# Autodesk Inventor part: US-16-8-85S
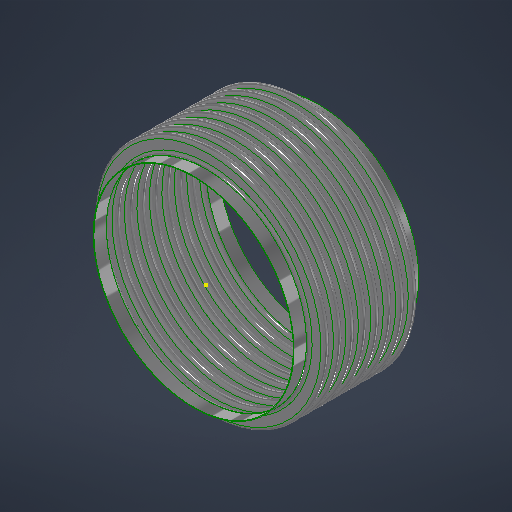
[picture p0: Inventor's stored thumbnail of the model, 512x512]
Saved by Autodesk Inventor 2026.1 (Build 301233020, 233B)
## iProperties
Category: 18 GA (0.048 THICK)
RuleStatus: InUse
Created: 2026-07
Part Number: US-16-8-85S
Project: =STOCK BELLOWS: <Stock Number><SFILL>
Material: ASTM A240-304
Description: =STOCK BELLOWS: <Stock Number>, <SID_> I.D., <SOD_> O.D., <SPLY_> PLY, <Category>, <SNET_CONS> CONS.<PITCH_><STANGENT_> TANGENT<SFILL>
Document SubType Name: Sheet Metal
Designer: LC
Stock Number: U.S-16-8-85S
Surface Area: 659.127 cm^2
Volume: 56.61 cm^3
Sheet Metal Rule: Default
Appearance: STAINLESS STEEL
NET_TUBE: 3.428
COUNTER: 1.500
PBAR: 1.214
PSET: 5.356
PLY: 2
CONS: 2
THK: 0.036
ID: 4.500
OD: 5.500
CONS_: 2
TANGENT: 0.500
PITCH: 0.375
BELLOWS_UPSET: 0.000
NET_CONS: 2
S_CONS: 0
Description_Units: 0
ID_M: 114.30 mm
OD_M: 139.70 mm
THK_M: 0.91 mm
ID_U: 4.500 in
OD_U: 5.500 in
THK_U: 0.036 in
TANGENT2: 0.500
d79: 1.000
d82: 1.000
d83: 26.000
d84: 24.000
d80: 2.571
d81: 10
SID: 2.375
SCONS_: 8
SPITCH: 0.250
SBELLOWS_UPSET: 0.000
SNET_CONS: 8
SS_CONS: 0
SCONS: 8
d174: 8
d177: 0.018
d178: 2.375
d179: 3.000
d180: 0.375
d181: 1.000
d182: 0.000
d190: 8
d191: 1
d192: 1
d193: 8
d194: 0
PART_NUMBER: U.S-16-8-85S
PRESSURE: 85
SIZE: 16.00
STANGENT_: 1.000
d214: 8
d217: 0.030
d218: 6.625
d219: 8.125
d220: 0.500
d221: 1.000
d222: 0.000
d230: 8
d231: 1
d232: 1
d233: 8
d234: 0
STANGENT: 4.000
SPLY_: 1
STHK_: 0.048
SID_: 16.000
SOD_: 18.500
SPITCH_: 1.000
STANGENT__: 1.000
SBELLOWS_UPSET_: 0.000
SDIFF_TAN: 1.000
TAN_TO_TAN: 0.750 in
d252: 2
d275: 2
d287: 0.050
d289: 0.500
d290: 0.000
d263: 2
d265: 1
d268: 2
d269: 0
d286: 2
d288: 1
d291: 2
d292: 0
SOD_NECK: 16 1/8
CFILL: .
SFILL: .
PITCH_: =, <SPITCH_> PITCH,
SREROLL: 0.750
MATTABLE: 20 GA (0.036 THICK)
MESH: ,
CSECT: 2
Author: LC
Keywords: 20 GA (0.036 THICK)
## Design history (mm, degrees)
sketch "Sketch2"
  geometry: L1 (0, -183.595)-(0, 600.956) reference; L2 (58.979, 0)-(57.15, 0); L3 (60.446, -1.467)-(66.554, -1.467); L4 (60.446, -3.296)-(66.554, -3.296); L5 (66.554, -8.058)-(60.446, -8.058); L6 (66.554, -6.229)-(60.446, -6.229); L7 (58.979, -9.525)-(57.15, -9.525); L8 (60.446, 0)-(60.446, -9.525); L9 (66.554, -4.762)-(69.85, -4.763); L10 (57.15, 0)-(57.15, -9.525); L11 (20.376, 102.841)-(20.376, 101.926); L12 (58.262, 488.877)-(58.262, 349.177); L13 (58.262, 479.352)-(58.262, 339.652); L14 (93.133, -58.817)-(93.133, -71.517); L15 (118.746, -66.401)-(118.746, -66.401); L16 (66.554, -6.229)-(66.554, -8.058); L17 (60.446, -6.229)-(60.446, -8.058); L18 (60.446, -7.144)-(66.554, -7.144); L19 (69.85, 0)-(69.85, -9.525); L20 (-66.554, -6.229)-(-66.554, -8.058); L21 (-66.554, -1.467)-(-60.446, -1.467); L22 (-66.554, -3.296)-(-60.446, -3.296); L23 (-60.446, -6.229)-(-66.554, -6.229); L24 (-66.554, -7.144)-(-60.446, -7.144); L25 (-60.446, -8.058)-(-66.554, -8.058); L26 (-60.446, -6.229)-(-60.446, -8.058); L27 (-57.15, -2.522)-(-57.15, -12.047); L28 (-60.446, -4.763)-(-57.15, -4.763); L29 (-66.554, 3.828)-(-66.554, -9.525); L30 (-68.021, 0)-(-69.85, 0); L31 (-69.85, 0)-(-69.85, -9.525); L32 (-68.021, -9.525)-(-69.85, -9.525); A1 r 1.467 centre (60.446, 0) between (58.979, 0) and (60.446, -1.467); A2 r 3.296 centre (60.446, 0) between (57.15, 0) and (60.446, -3.296); A3 r 3.296 centre (66.554, -4.762) between (66.554, -8.058) and (66.554, -1.467); A4 r 1.467 centre (66.554, -4.762) between (66.554, -6.229) and (66.554, -3.296); A5 r 1.467 centre (60.446, -9.525) between (60.446, -8.058) and (58.979, -9.525); A6 r 3.296 centre (60.446, -9.525) between (60.446, -6.229) and (57.15, -9.525); A7 r 2.381 centre (66.554, -4.762) between (66.554, -7.144) and (68.936, -4.762); A8 r 2.381 centre (60.446, -9.525) between (60.446, -7.144) and (58.064, -9.525); A9 r 1.467 centre (-66.554, -9.525) between (-66.554, -8.058) and (-68.021, -9.525); A10 r 1.467 centre (-60.446, -4.763) between (-60.446, -6.229) and (-60.446, -3.296); A11 r 2.381 centre (-60.446, -4.763) between (-60.446, -7.144) and (-58.064, -4.763); A12 r 3.296 centre (-60.446, -4.763) between (-60.446, -8.058) and (-60.446, -1.467); A13 r 2.381 centre (-66.554, -9.525) between (-66.554, -7.144) and (-68.936, -9.525); A14 r 3.296 centre (-66.554, -9.525) between (-66.554, -6.229) and (-69.85, -9.525); A15 r 1.467 centre (-66.554, 0) between (-68.021, 0) and (-66.554, -1.467); A16 r 3.296 centre (-66.554, 0) between (-69.85, 0) and (-66.554, -3.296); 10 further points
  constraints: 62 end point, 38 point on circle, 20 tangent, 16 centre point, 12 parallel, 9 midpoint, 7 vertical, 6 coincident, 6 concentric, 6 point on line, 4 equal radius, 4 perpendicular, 3 horizontal, 1 collinear, 1 horizontal alignment, 10 other
  dimensions: "THK" = 0.9144 distance of L11.start L11.end; "ID" = 114.3 distance of L11.end point (20.376, -12.374); "OD" = 139.7 distance of L12.start L12.end; "PITCH" = 9.525 distance of L12.start L13.start; "TANGENT" = 12.7 distance of L14.start L14.end; "BELLOWS_UPSET" = 0 distance of L15.start L15.end; "d43" = 114.3 diameter of L10 L1 (= ID); "d44" = 139.7 diameter of L9.end L1 (= OD); "d45" = 1.8288 distance between parallel lines of L5 L6 (computed from THK, PLY); "d46" = 3.29565 radius of A3 (computed from PITCH, THK, PLY); "UPSET_PITCH" = 9.525 distance of L2.end L7.end (derived); "SIDEWALL_ANGLE" = 0 deg angle of L3 L9 (derived); "CON_GAP" = 2.9337 distance of point (60.446, -6.229) point (60.446, -3.296) (derived); "TAN1" = 3.74046 dimension on A8 (derived); "TAN2" = 3.74046 dimension on A7 (derived); "LEG1" = 6.1087 distance of L18.start L18.end (derived); "d278" = 1.8288 distance between parallel lines of L25 L23 (derived); "d279" = 3.29565 radius of A12 (derived); "d280" = 9.525 distance of L30.end L31.end (derived); "d281" = 360 deg dimension on L21 L28 (derived); "d282" = 2.9337 distance of point (-66.554, -6.229) point (-66.554, -3.296) (derived); "d283" = 3.74046 dimension on A13 (derived); "d284" = 3.74046 dimension on A11 (derived); "d285" = 6.1087 distance of L24.start L24.end (derived); "d293" = 114.3 diameter of L27 L1 (derived); "d294" = 139.7 diameter of L31 L1 (derived)
  node "Sketch Rectangular Pattern1" dims "d31" = 25.4, "ID" = 114.3
  node "Sketch Rectangular Pattern2" dims "d39" = 25.4, "PITCH" = 9.525
revolve "CONS" stored, may be unused: angle "d48" = 90 deg
node "BELLOW MIDPLANE"
pattern_linear "Rectangular Pattern2" dims "d52" = 9.525 (= UPSET_PITCH)
sketch "Sketch5"
  geometry: C1 r 58.979 at (0, 0) reference; C2 r 57.15 at (0, 0) reference
extrude "TANGENT" new body sketch "Sketch5" distance "d53" = 12.7 (= TANGENT); taper "d54" = 0 deg
revolve "SAMETAN" stored, may be unused: angle "d65" = 90 deg
revolve "DIFFTAN" stored, may be unused: angle "d70" = 90 deg
sketch "Sketch9"
  geometry: L1 (58.391, 0)-(-58.391, 0) reference; L2 (0, -17.78)-(0, 17.78) reference; L3 (41.708, 0)-(-41.708, 0); L4 (41.708, -11.906)-(41.708, 11.906); L5 (29.008, -11.906)-(29.008, 11.906); L6 (15.418, 11.906)-(15.418, -11.906); L7 (-29.008, -11.906)-(-29.008, 11.906); L8 (-41.708, -11.906)-(-41.708, 11.906); L9 (40.914, -11.906)-(40.914, 11.906); L10 (41.708, -11.906)-(40.914, -11.906); L11 (41.708, 11.906)-(40.914, 11.906); L12 (15.815, 11.906)-(15.022, 11.906); L13 (15.022, 11.906)-(15.022, -11.906); L14 (15.022, -11.906)-(15.815, -11.906); L15 (15.815, -11.906)-(15.815, 11.906); L16 (-15.815, 11.906)-(-15.815, -11.906); L17 (-15.418, 11.906)-(-15.418, -11.906); L18 (-15.815, -11.906)-(-15.022, -11.906); L19 (-15.022, -11.906)-(-15.022, 11.906); L20 (-15.022, 11.906)-(-15.815, 11.906); L21 (-41.708, -11.906)-(-40.914, -11.906); L22 (-40.914, -11.906)-(-40.914, 11.906); L23 (-40.914, 11.906)-(-41.708, 11.906); L24 (-41.708, 11.906)-(-41.708, -11.906); L25 (41.708, -0.397)-(-41.708, -0.397); L26 (-41.708, -0.397)-(-41.708, 0.397); L27 (-41.708, 0.397)-(41.708, 0.397); L28 (41.708, 0.397)-(41.708, -0.397); L29 (-41.708, 11.906)-(41.708, 11.906); L30 (41.708, 11.906)-(41.708, 12.7); L31 (41.708, 12.7)-(-41.708, 12.7); L32 (-41.708, 12.7)-(-41.708, 11.906); L33 (41.708, -11.906)-(-41.708, -11.906); L34 (-41.708, -11.906)-(-41.708, -12.7); L35 (-41.708, -12.7)-(41.708, -12.7); L36 (41.708, -12.7)-(41.708, -11.906); 30 further points
  constraints: 68 end point, 13 midpoint, 13 parallel, 8 horizontal, 7 perpendicular, 6 equal length, 3 point on line, 2 vertical, 14 other
  dimensions: "d115" = 23.8125 distance of L4.start L4.end (derived); "d116" = 12.7 distance between parallel lines of L4 L5 (derived); "d117" = 13.58962 distance between parallel lines of L5 L6 (derived); "d125" = 44.42645 distance between parallel lines of L7 L6 (derived); "d127" = 12.7 distance between parallel lines of L8 L7 (derived); "d128" = 26.28962 distance between parallel lines of L6 L4 (derived); "d130" = 83.41607 distance between parallel lines of L8 L4 (derived); "RULER_THK" = 0.79375 distance between parallel lines of L4 L9; "d135" = 0.79375 distance of L13.end L14.end (derived); "d138" = 30.83684 distance of L13.end L16.end (derived); "d143" = 0.79375 distance of L22.end L8.end (derived); "d144" = 0.79375 distance between parallel lines of L27 L25 (derived)
extrude "RULER" join sketch "Sketch9" distance "d149" = 0.79375 (derived); taper "d150" = 0 deg
extrude "BARS" join sketch "Sketch9" distance "d151" = 0.79375 (derived); taper "d152" = 0 deg
pattern_linear "Rectangular Pattern4" dims "d155" = 30.83684 (derived)
sketch "Sketch13"
  geometry: L1 (93.149, -52.467)-(93.149, -77.867); L2 (204.419, 0)-(203.2, 0); L3 (204.419, -25.4)-(203.2, -25.4); L4 (227.99, -19.66)-(210.16, -19.66); L5 (227.99, -18.44)-(210.16, -18.44); L6 (227.99, -12.7)-(234.95, -12.7); L7 (210.16, -5.74)-(227.99, -5.74); L8 (210.16, 0)-(210.16, -25.4); L9 (203.2, 0)-(203.2, -25.4); L10 (58.254, -237.139)-(58.254, -707.039); L11 (58.254, -262.539)-(58.254, -732.439); L12 (58.254, -313.339)-(58.254, -783.239); L13 (58.254, -338.739)-(58.254, -808.639); L14 (58.254, -364.139)-(58.254, -834.039); L15 (58.254, -389.539)-(58.254, -859.439); L16 (58.254, -414.939)-(58.254, -884.839); L17 (58.254, -287.939)-(58.254, -757.839); L18 (20.376, 103.145)-(20.376, 101.926); L19 (210.16, -6.96)-(227.99, -6.96); L20 (0, -1034.115)-(0, 292.333) reference; L21 (-40.958, 0)-(245.745, 0) reference; A1 r 5.74 centre (210.16, 0) between (204.419, 0) and (210.16, -5.74); A2 r 5.74 centre (210.16, -25.4) between (210.16, -19.66) and (204.419, -25.4); A3 r 6.96 centre (210.16, -25.4) between (210.16, -18.44) and (203.2, -25.4); A4 r 5.74 centre (227.99, -12.7) between (227.99, -18.44) and (227.99, -6.96); A5 r 6.96 centre (227.99, -12.7) between (227.99, -19.66) and (227.99, -5.74); A6 r 6.96 centre (210.16, 0) between (203.2, 0) and (210.16, -6.96); 6 further points; 1 other entity
  constraints: 38 end point, 15 point on circle, 9 tangent, 6 centre point, 6 parallel, 5 vertical alignment, 4 point on line, 4 vertical, 3 coincident, 3 concentric, 2 collinear, 2 equal radius, 1 horizontal, 1 perpendicular, 23 other
  dimensions: "SBELLOWS_UPSET_" = 0 distance of point (118.762, -66.401) point (118.762, -66.401); "STOTAL_THK_BELLOW__" = 1.2192 distance between parallel lines of L4 L5 (derived); "d224" = 6.9596 radius of A5 (derived); "d225" = 25.4 distance of L2.end L3.end (derived); "SSIDEWALL_ANGLE_" = 0 deg angle of L7 L6 (derived); "SSCON_GAP_" = 11.4808 distance of point (210.16, -18.44) point (210.16, -6.96) (derived); "d235" = 406.4 diameter of L9 L20 (derived); "d236" = 469.9 diameter of L6.end L20 (derived)
  node "Sketch Rectangular Pattern4" dims "d228" = 25.4
  node "Sketch Rectangular Pattern5" dims "d229" = 25.4
revolve "SBELLOW" stored, may be unused: angle "d197" = 90 deg
pattern_linear "Rectangular Pattern5" dims "d204" = 25.4 (derived)
revolve "STANGENT" stored, may be unused: angle "d240" = 90 deg
revolve "SSAMETAN" stored, may be unused: angle "d241" = 90 deg
revolve "SDIFFTAN" stored, may be unused: angle "d246" = 90 deg
revolve "INVCON" stored, may be unused: angle "d295" = 90 deg
pattern_linear "Rectangular Pattern6" dims "d298" = 9.525 (derived)
revolve "INVTANGENT" stored, may be unused: angle "d302" = 90 deg
revolve "INVSAMETAN" stored, may be unused: angle "d307" = 90 deg
revolve "INVDIFFTAN" stored, may be unused: angle "d312" = 90 deg
sketch "ID BELLOW MOUNT CALC"
  geometry: L1 (44.45, 0)-(38.1, 0); L2 (38.1, 0)-(38.1, 12.7); L3 (38.1, 12.7)-(44.45, 12.7); L4 (44.45, 12.7)-(44.45, 0); L5 (36.513, 12.7)-(34.684, 12.7); L6 (34.684, 12.7)-(34.684, 0); L7 (34.684, 0)-(36.513, 0); L8 (36.513, 0)-(36.513, 12.7); L9 (0, -2.54)-(0, 15.24) reference; L10 (-8.89, 0)-(53.34, 0) reference; 1 further point
  constraints: 16 end point, 5 parallel, 2 collinear, 2 horizontal, 2 perpendicular
  dimensions: "d314" = 12.7 distance of L5.end L6.end (derived); "d315" = 1.8288 distance of L5.start L5.end (derived); "IG" = 1.5875 distance between parallel lines of L2 L8; "PIPE_OD" = 88.9 diameter of L4 L9; "PIPE_WALL" = 6.35 distance of L2.end L3.end; "ID_MT_BELLOW" = 69.3674 diameter of L6 L9 (derived)
revolve "CFILL" stored, may be unused: angle "d320" = 90 deg
pattern_linear "Rectangular Pattern7" dims "d323" = 9.525 (derived)
revolve "SFILL" stored, may be unused: angle "d324" = 90 deg
pattern_linear "Rectangular Pattern8" dims "d327" = 25.4 (derived)
node "STOCK BELLOW MIDPLANE"
sketch "Sketch21"
  geometry: L1 (0, -100.013)-(0, 100.013) reference; L2 (-100.013, 0)-(100.013, 0) reference; L3 (-0.099, 71.437)-(0.099, 71.437); L4 (0.099, 71.437)-(0.099, 55.562); L5 (0.099, 55.562)-(-0.099, 55.562); L6 (-0.099, 55.562)-(-0.099, 71.437); C1 r 55.562 at (0, 0); C2 r 71.437 at (0, 0); 3 further points
  constraints: 8 end point, 2 centre point, 2 coincident, 2 parallel, 2 tangent, 1 horizontal, 1 perpendicular, 1 other
  dimensions: "d329" = 111.125 diameter of C1 (derived); "d330" = 142.875 diameter of C2 (derived); "d331" = 0.19844 distance of L3.start L3.end
extrude "CLAMSHELL" cut sketch "Sketch21" extent not by distance; stored distance "d332" = 0; taper "d333" = 0 deg
pattern_circular "Circular Pattern1" dims angle "d335" = 180 deg (derived)
node "BELLOW"
sketch "Sketch6"
  geometry: L1 (-19.05, 58.979)-(-6.35, 58.979); L2 (-6.35, 58.979)-(-6.35, 57.15); L3 (-6.35, 57.15)-(-19.05, 57.15); L4 (-19.05, 57.15)-(-19.05, 58.979); L5 (2.54, 0)-(-59.69, 0) reference; L6 (-38.1, -108.388)-(-38.1, 156.601) reference; 1 further point
  constraints: 8 end point, 2 parallel, 1 horizontal, 1 perpendicular
  dimensions: "d61" = 12.7 distance of L2.end L3.end (derived); "d62" = 1.8288 distance of L1.end L2.end (derived); "d63" = 114.3 diameter of L3 L5 (derived); "d64" = 19.05 distance between parallel lines of L4 L6 (derived)
sketch "Sketch12"
  geometry: 1 further point
sketch "Sketch14"
  geometry: L1 (-25.4, 204.419)-(0, 204.419); L2 (0, 204.419)-(0, 203.2); L3 (0, 203.2)-(-25.4, 203.2); L4 (-25.4, 203.2)-(-25.4, 204.419); L5 (5.08, 0)-(-30.48, 0) reference; L6 (0, -35.743)-(0, 214.457) reference; 1 further point
  constraints: 8 end point, 2 parallel, 1 collinear, 1 horizontal, 1 perpendicular
  dimensions: "d237" = 1.2192 distance of L3.end L1.start (derived); "d238" = 406.4 diameter of L3 L5 (derived); "d239" = 25.4 distance of L1.start L1.end (derived); "SOD_NECK" = 408.8384 diameter of L1 L5 (derived)
sketch "Sketch15"
  geometry: L1 (-35.743, 0)-(214.457, 0) reference; L2 (203.2, -203.2)-(204.419, -203.2); L3 (204.419, -203.2)-(204.419, -228.6); L4 (204.419, -228.6)-(203.2, -228.6); L5 (203.2, -228.6)-(203.2, -203.2); L6 (0, -276.86)-(0, 60.96) reference; 1 further point
  constraints: 8 end point, 2 parallel, 1 horizontal, 1 perpendicular
  dimensions: "d205" = 25.4 distance of L4.end L2.start (derived); "d206" = 1.2192 distance of L3.end L4.end (derived); "d207" = 406.4 diameter of L5 L6 (derived); "d208" = 203.2 distance between parallel lines of L1 L2 (derived)
node "TANGENT_"
node "SAME_TAN"
sketch "Sketch8"
  geometry: L1 (58.979, -19.05)-(57.15, -19.05); L2 (57.15, -19.05)-(57.15, -31.75); L3 (57.15, -31.75)-(58.979, -31.75); L4 (58.979, -31.75)-(58.979, -19.05); L5 (0, -40.64)-(0, 21.59) reference; L6 (-108.388, 0)-(156.601, 0) reference; 1 further point
  constraints: 8 end point, 2 parallel, 1 horizontal, 1 perpendicular
  dimensions: "d66" = 114.3 diameter of L2 L5 (derived); "TOTAL_THK_BELLOW" = 1.8288 distance of L2.end L3.end (derived); "d68" = 19.05 distance between parallel lines of L1 L6 (derived); "d69" = 12.7 distance of L1.end L2.end (derived)
node "DIFF_TAN"
node "Sketch Rectangular Pattern3" dims "d138" = 30.83684 (derived), "d141" = 25.4
node "SBELLOW_"
node "STANGENT_"
node "SSAME_TAN"
sketch "Sketch16"
  geometry: L1 (204.419, -203.2)-(203.2, -203.2); L2 (203.2, -203.2)-(203.2, -228.6); L3 (203.2, -228.6)-(204.419, -228.6); L4 (204.419, -228.6)-(204.419, -203.2); L5 (0, -276.86)-(0, 60.96) reference; L6 (-35.743, 0)-(214.457, 0) reference; 1 further point
  constraints: 8 end point, 2 parallel, 1 horizontal, 1 perpendicular
  dimensions: "SDIFF_TAN" = 25.4 distance of L3.end L1.start; "d243" = 1.2192 distance of L2.end L3.end (derived); "d244" = 203.2 distance between parallel lines of L1 L6 (derived); "d245" = 406.4 diameter of L2 L5 (derived)
node "SDIFF_TAN"
body "Solid15"
sketch "Sketch17"
  geometry: L1 (69.85, 12.7)-(68.021, 12.7); L2 (68.021, 12.7)-(68.021, 0); L3 (68.021, 0)-(69.85, 0); L4 (69.85, 0)-(69.85, 12.7); L5 (0, -2.54)-(0, 15.24) reference; L6 (-13.97, 0)-(83.82, 0) reference; 2 further points
  constraints: 8 end point, 2 parallel, 1 horizontal, 1 midpoint, 1 perpendicular, 1 point on line
  dimensions: "INVTANGENT" = 12.7 distance of L3.end L1.start (derived); "d300" = 1.8288 distance of L1.start L1.end (derived); "d301" = 139.7 diameter of L4 L5 (derived)
body "Solid16"
sketch "Sketch18"
  geometry: L1 (69.85, -19.05)-(68.021, -19.05); L2 (68.021, -19.05)-(68.021, -31.75); L3 (68.021, -31.75)-(69.85, -31.75); L4 (69.85, -31.75)-(69.85, -19.05); L5 (-13.97, 0)-(83.82, 0) reference; L6 (0, -40.64)-(0, 21.59) reference; 1 further point
  constraints: 8 end point, 2 parallel, 1 horizontal, 1 perpendicular
  dimensions: "d303" = 19.05 distance between parallel lines of L1 L5 (derived); "d304" = 12.7 distance of L3.end L1.start (derived); "d305" = 1.8288 distance of L2.end L3.end (derived); "d306" = 139.7 diameter of L4 L6 (derived)
body "Solid17"
sketch "Sketch19"
  geometry: L1 (69.85, -19.05)-(68.021, -19.05); L2 (68.021, -19.05)-(68.021, -31.75); L3 (68.021, -31.75)-(69.85, -31.75); L4 (69.85, -31.75)-(69.85, -19.05); L5 (0, -40.64)-(0, 21.59) reference; L6 (-13.97, 0)-(83.82, 0) reference; 1 further point
  constraints: 8 end point, 2 parallel, 1 horizontal, 1 perpendicular
  dimensions: "d308" = 12.7 distance of L1.end L2.end (derived); "d309" = 139.7 diameter of L4 L5 (derived); "d310" = 1.8288 distance of L2.end L3.end (derived); "d311" = 19.05 distance between parallel lines of L1 L6 (derived)
body "Solid18"
body "Solid19"
body "Solid20"
other parameters: "BMPL" = -101.6, "PSET" = 136.0424 (computed from OD, THK, PLY) [user parameter], "PBAR" = 30.83684 (= 0.570796 x PITCH + OD - ID) [user parameter; used in 1 equation term], "COUNTER" = 15 [user parameter], "NET_TUBE" = 87.07367 (computed from CONS_, PBAR, TANGENT) [user parameter], "S_CONS" = 0 [user parameter; used in 1 equation term], "ID_M" = 114.3 (= ID) [user parameter], "OD_M" = 139.7 (= OD) [user parameter], "THK_M" = 0.9144 (= THK) [user parameter], "ID_U" = 114.3 (= ID) [user parameter], "OD_U" = 139.7 (= OD) [user parameter], "THK_U" = 0.9144 (= THK) [user parameter], "D_UNITS" = 0 [user parameter], "TANGENT2" = 12.7 [user parameter], "TAN_TO_TAN" = 19.05 [user parameter], "OD_NECK" = 117.9576 [user parameter], "d79" = 25.4, "d80" = 65.29823 [user parameter], "d82" = 25.4, "d83" = 660.4, "d84" = 609.6, "sa_0" = 4, "FRAME_THK" = 0.79375 [user parameter], "CON_FLAT" = 13.58962 [user parameter], "SID" = 60.325 [user parameter], "SPITCH" = 6.35 [user parameter], "STANGENT_" = 25.4 [user parameter], "SBELLOWS_UPSET" = 0 [user parameter], "SS_CONS" = 0 [user parameter], "STAN_TO_TAN_" = 203.2 [user parameter], "d100" = 1.2192 [user parameter], "d191" = 25.4 [user parameter], "d194" = 0 [user parameter], "STANGENT" = 101.6 [user parameter], "d234" = 0 [user parameter], "SUPSET_PITCH_" = 25.4 [user parameter], "d269" = 0 [user parameter], "d287" = 1.27, "d289" = 12.7, "d290" = 0, "d292" = 0 [user parameter], "Thickness" = 3.048 (derived), "KFactor" = 4.4, "BendRadius" = 3.048 (derived), "BendReliefWidth" = 3.048 (derived), "BendReliefDepth" = 1.524 (derived), "CornerReliefSize" = 12.192 (derived), "SeamGap" = 0.00508, "MinimumRemnant" = 6.096 (derived), "TransitionRadius" = 3.048 (derived), "JacobiRadiusSize" = 3.048 (derived), "GapSize" = 3.048 (derived), "SREROLL" = 19.05 [user parameter], "CUR_STK_PITCH" = 25.4 [user parameter], "d328" = -101.6 (derived), "CSECTDEG" = 180 deg [user parameter]
